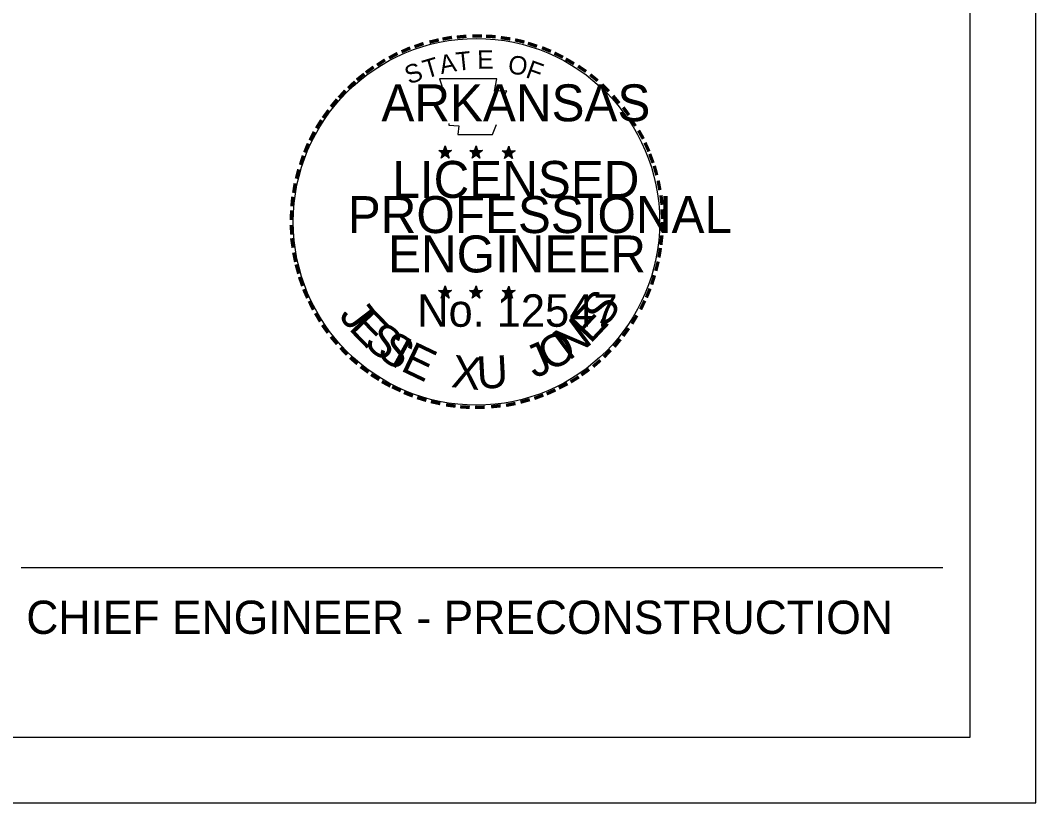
# Model space of a CAD drawing. Extents: x -819161 to 80911, y -6604 to 768454.
# Drawn here: x 48407 to 52278, y -340 to 2641 of the extents above; entities that cross this region are included whole.
import ezdxf

# ---------------------------------------------------------------- set-up
doc = ezdxf.new("R2010")
doc.units = 0
for name, color, linetype in [('29', 7, 'Continuous'), ('31', 7, 'Continuous'), ('Default', 7, 'Continuous'), ('DSN_DRFT_Junk-No-Plot', 7, 'Continuous'), ('SHET_Border-Lines', 7, 'Continuous')]:
    doc.layers.add(name, color=color, linetype=linetype)

msp = doc.modelspace()

# ---------------------------------------------------------------- linework, layer by layer
at = {"layer": '29'}
for p, q in [((50002.4, 2144.7), (50027, 2136.8)), ((50002.4, 2144.7), (50020.5, 2141.8)), ((50002.4, 2144.7), (50019.1, 2136)), ((50011.8, 2115.8), (50027, 2136.8)), ((50011.8, 2115.8), (50020.5, 2133.1)), ((50011.8, 2115.8), (50026.3, 2131)), ((50027, 2162.8), (50024.1, 2144.7)), ((50042.2, 2115.8), (50026.3, 2131)), ((50027, 2136.8), (50027, 2162.8)), ((50027, 2162.8), (50030.6, 2145.5)), ((50050.9, 2144.7), (50027, 2136.8)), ((50042.2, 2115.8), (50027, 2136.8)), ((50050.9, 2144.7), (50031.4, 2141.1)), ((50042.2, 2115.8), (50032.1, 2136)), ((50050.9, 2144.7), (50037.2, 2137.5)), ((50120.4, 2144.7), (50145.1, 2136.8)), ((50120.4, 2144.7), (50137.8, 2141.8)), ((50120.4, 2144.7), (50136.4, 2136)), ((50129.1, 2115.8), (50145.1, 2136.8)), ((50129.1, 2115.8), (50138.5, 2133.1)), ((50129.1, 2115.8), (50144.3, 2131)), ((50145.1, 2162.8), (50142.2, 2144.7)), ((50159.5, 2115.8), (50144.3, 2131)), ((50145.1, 2136.8), (50145.1, 2162.8)), ((50145.1, 2162.8), (50148, 2145.5)), ((50169, 2144.7), (50145.1, 2136.8)), ((50159.5, 2115.8), (50145.1, 2136.8)), ((50169, 2144.7), (50148.7, 2141.1)), ((50159.5, 2115.8), (50149.4, 2136)), ((50169, 2144.7), (50154.5, 2137.5)), ((50244.3, 2144), (50268.9, 2136)), ((50244.3, 2144), (50261.7, 2140.4)), ((50244.3, 2144), (50260.9, 2135.3)), ((50253, 2115), (50268.9, 2136)), ((50253, 2115), (50262.4, 2132.4)), ((50253, 2115), (50268.9, 2130.2)), ((50268.9, 2161.4), (50266, 2144)), ((50268.9, 2136), (50268.9, 2161.4)), ((50268.9, 2161.4), (50271.8, 2144)), ((50293.5, 2144), (50268.9, 2136)), ((50283.4, 2115), (50268.9, 2136)), ((50283.4, 2115), (50268.9, 2130.2)), ((50293.5, 2144), (50272.5, 2140.4)), ((50283.4, 2115), (50274, 2135.3)), ((50293.5, 2144), (50278.3, 2136.8)), ((50026.3, 1629.1), (50023.4, 1611.7)), ((50026.3, 1603.8), (50026.3, 1629.1)), ((50026.3, 1629.1), (50029.9, 1611.7)), ((50144.3, 1629.1), (50141.4, 1611.7)), ((50144.3, 1603.8), (50144.3, 1629.1)), ((50144.3, 1629.1), (50147.2, 1611.7)), ((50268.9, 1628.4), (50266, 1611)), ((50268.9, 1603), (50268.9, 1628.4)), ((50268.9, 1628.4), (50271.8, 1611)), ((50001.7, 1611.7), (50026.3, 1603.8)), ((50001.7, 1611.7), (50020.5, 1608.1)), ((50001.7, 1611.7), (50019.1, 1603)), ((50011.8, 1582.8), (50026.3, 1603.8)), ((50011.8, 1582.8), (50020.5, 1600.2)), ((50011.8, 1582.8), (50026.3, 1598.7)), ((50050.9, 1611.7), (50026.3, 1603.8)), ((50042.2, 1582.8), (50026.3, 1603.8)), ((50042.2, 1582.8), (50026.3, 1598)), ((50050.9, 1611.7), (50030.6, 1608.1)), ((50042.2, 1582.8), (50032.1, 1603)), ((50050.9, 1611.7), (50037.2, 1604.5)), ((50119.7, 1611.7), (50144.3, 1603.8)), ((50119.7, 1611.7), (50137.8, 1608.1)), ((50119.7, 1611.7), (50136.4, 1603)), ((50129.1, 1582.8), (50144.3, 1603.8)), ((50129.1, 1582.8), (50137.8, 1600.2)), ((50129.1, 1582.8), (50144.3, 1598.7)), ((50169, 1611.7), (50144.3, 1603.8)), ((50158.8, 1582.8), (50144.3, 1603.8)), ((50158.8, 1582.8), (50144.3, 1598)), ((50169, 1611.7), (50148, 1608.1)), ((50158.8, 1582.8), (50149.4, 1603)), ((50169, 1611.7), (50153.8, 1604.5)), ((50244.3, 1611), (50268.9, 1603)), ((50244.3, 1611), (50261.7, 1607.4)), ((50244.3, 1611), (50260.9, 1602.3)), ((50253, 1582), (50268.9, 1603)), ((50253, 1582), (50262.4, 1599.4)), ((50253, 1582), (50268.9, 1598)), ((50293.5, 1611), (50268.9, 1603)), ((50283.4, 1582), (50268.9, 1603)), ((50283.4, 1582), (50268.9, 1597.3)), ((50293.5, 1611), (50272.5, 1607.4)), ((50283.4, 1582), (50273.2, 1602.3)), ((50293.5, 1611), (50278.3, 1603.8)), ((48410.7, 556.2), (51924.5, 556.2))]:
    msp.add_line(p, q, dxfattribs=at)
for points in [[(50005.3, 2417.7), (50024.1, 2359.1)], [(50252.2, 2353.3), (50262.4, 2372.8), (50214.6, 2371.4), (50224, 2417.7), (50005.3, 2417.7)], [(50040.1, 2247.6), (50040.1, 2241), (50079.2, 2239.6), (50075.5, 2206.3), (50207.3, 2206.3), (50221.8, 2243.9)], [(50026.3, 1629.1), (50042.2, 1582.8), (50001.7, 1611.7), (50050.9, 1611.7), (50011.8, 1582.8), (50026.3, 1629.1)], [(50268.9, 1628.4), (50283.4, 1582), (50244.3, 1611), (50293.5, 1611), (50253, 1582), (50268.9, 1628.4)]]:
    msp.add_lwpolyline(points, dxfattribs=at)
for centre, radius in [((50146, 1873.2), 698.5), ((50026.4, 2136.7), 12.1), ((50026.4, 2136.7), 10.2), ((50026.4, 2136.7), 8.15), ((50026.4, 2136.7), 6.97), ((50026.4, 2136.7), 5.26), ((50026.4, 2136.7), 3.49), ((50026.4, 2136.7), 2.09), ((50143.9, 2136.7), 12.1), ((50143.9, 2136.7), 10.2), ((50143.9, 2136.7), 8.15), ((50143.9, 2136.7), 6.97), ((50143.9, 2136.7), 5.26), ((50143.9, 2136.7), 3.49), ((50143.9, 2136.7), 2.09), ((50268.1, 2135.8), 12.1), ((50268.1, 2135.8), 10.2), ((50268.1, 2135.8), 8.15), ((50268.1, 2135.8), 6.97), ((50268.1, 2135.8), 5.26), ((50268.1, 2135.8), 3.49), ((50268.1, 2135.8), 2.09), ((50026.1, 1603.6), 12.1), ((50026.1, 1603.6), 10.2), ((50026.1, 1603.6), 8.15), ((50026.1, 1603.6), 6.97), ((50026.1, 1603.6), 5.26), ((50026.1, 1603.6), 3.49), ((50026.1, 1603.6), 2.09), ((50143.6, 1603.6), 12.1), ((50143.6, 1603.6), 10.2), ((50143.6, 1603.6), 8.15), ((50143.6, 1603.6), 6.97), ((50143.6, 1603.6), 5.26), ((50143.6, 1603.6), 3.49), ((50143.6, 1603.6), 2.09), ((50268, 1602.9), 12.1), ((50268, 1602.9), 10.2), ((50268, 1602.9), 8.15), ((50268, 1602.9), 6.97), ((50268, 1602.9), 5.26), ((50268, 1602.9), 3.49), ((50268, 1602.9), 2.09)]:
    msp.add_circle(centre, radius, dxfattribs=at)
at = {"layer": '31'}
for points in [[(50027, 2162.8), (50042.2, 2115.8), (50002.4, 2144.7), (50050.9, 2144.7), (50011.8, 2115.8), (50027, 2162.8)], [(50145.1, 2162.8), (50159.5, 2115.8), (50120.4, 2144.7), (50169, 2144.7), (50129.1, 2115.8), (50145.1, 2162.8)], [(50268.9, 2161.4), (50283.4, 2115), (50244.3, 2144), (50293.5, 2144), (50253, 2115), (50268.9, 2161.4)], [(50144.3, 1629.1), (50158.8, 1582.8), (50119.7, 1611.7), (50169, 1611.7), (50129.1, 1582.8), (50144.3, 1629.1)]]:
    msp.add_lwpolyline(points, dxfattribs=at)
at = {"layer": 'Default'}
msp.add_lwpolyline([(35278.1, 10659.9), (35278.1, -340.1), (52278.1, -340.1), (52278.1, 10659.9)], close=True, dxfattribs=at)
at = {"layer": 'DSN_DRFT_Junk-No-Plot'}
msp.add_lwpolyline([(35278.1, -340.1), (52278.1, -340.1), (52278.1, 10659.9), (35278.1, 10659.9)], close=True, dxfattribs=at)
at = {"layer": 'SHET_Border-Lines'}
msp.add_lwpolyline([(35528.1, -90.1), (52028.1, -90.1), (52028.1, 10409.9), (35528.1, 10409.9)], close=True, dxfattribs=at)
msp.add_lwpolyline([(35528.1, -90.1), (52028.1, -90.1), (52028.1, 10409.9), (35528.1, 10409.9)], close=True, dxfattribs=at)

# ---------------------------------------------------------------- texts
at = {"layer": '29'}
for s, height, rotation, p in [('-', 112.6, 19.1761, (49917.7, 2497.4)), ('-', 112.6, 13.6301, (49970.5, 2514.1)), ('-', 112.6, 10.2193, (50017.6, 2525.6)), ('-', 112.6, 5.8968, (50069, 2532.9)), ('-', 112.6, 0.1862, (50123.3, 2538)), ('-', 112.6, 357.743, (50174, 2537.2)), ('-', 112.6, 352.1617, (50226.2, 2532.9)), ('-', 112.6, 347.2049, (50276.9, 2525.6)), ('-', 112.6, 342.3362, (50322.5, 2514.1)), ('-', 112.6, 28.7918, (49827.9, 2456.1)), ('-', 112.6, 24.3072, (49872.1, 2478.6)), ('T', 70.4, 6.0228, (50071.2, 2448.2)), ('E', 70.4, 0.8323, (50149.4, 2456.1)), ('-', 112.6, 337.8551, (50373.2, 2498.9)), ('-', 112.6, 334.1211, (50418.1, 2480)), ('-', 112.6, 34.0636, (49785.9, 2430.1)), ('S', 70.4, 21.594, (49889.4, 2395.3)), ('T', 70.4, 16.4036, (49953.9, 2418.5)), ('A', 70.4, 11.2132, (50011.8, 2435.8)), ('O', 70.4, 350.4515, (50262.4, 2440.9)), ('F', 70.4, 340.0707, (50329.7, 2425)), ('-', 112.6, 329.6409, (50458.6, 2459.7)), ('-', 112.6, 38.9507, (49712, 2375.7)), ('-', 112.6, 36.2317, (49744.6, 2402.5)), ('-', 112.6, 325.8627, (50503.5, 2434.4)), ('-', 112.6, 320.5297, (50547, 2404.7)), ('-', 112.6, 42.9622, (49681.6, 2346)), ('-', 112.6, 315.5786, (50589, 2369.9)), ('-', 112.6, 48.4231, (49649.7, 2312)), ('-', 112.6, 50.6142, (49620.8, 2278.7)), ('-', 112.6, 309.8797, (50628.8, 2330.8)), ('-', 112.6, 54.2325, (49592.5, 2238.1)), ('-', 112.6, 306.6522, (50666.5, 2288.8)), ('-', 112.6, 58.0706, (49569.3, 2201.2)), ('-', 98.5, 303.6753, (50699.8, 2249)), ('-', 112.6, 62.8713, (49546.9, 2157.8)), ('-', 112.6, 299.6684, (50723, 2205.6)), ('-', 112.6, 67.7743, (49528.8, 2115)), ('-', 112.6, 294.6628, (50746.1, 2162.8)), ('-', 112.6, 290.5728, (50763.5, 2123)), ('-', 112.6, 72.3945, (49514.3, 2070.9)), ('-', 112.6, 75.461, (49499.8, 2020.2)), ('-', 112.6, 285.1233, (50780.2, 2081.7)), ('-', 112.6, 81.2013, (49491.1, 1970.2)), ('-', 112.6, 280.5493, (50794.7, 2028.9)), ('-', 112.6, 276.5962, (50805.5, 1976)), ('-', 112.6, 85.1863, (49485.3, 1921.7)), ('-', 112.6, 89.0622, (49483.9, 1872.4)), ('-', 112.6, 274.3301, (50809.9, 1924.6)), ('-', 112.6, 94.1959, (49486.1, 1821)), ('-', 112.6, 269.9407, (50812, 1879.7)), ('-', 112.6, 263.5172, (50810.6, 1833.3)), ('-', 112.6, 98.9479, (49491.1, 1774.7)), ('-', 112.6, 101.7149, (49500.6, 1722.5)), ('-', 112.6, 260.9953, (50805.5, 1787)), ('-', 112.6, 105.4578, (49512.1, 1680.5)), ('-', 112.6, 255.7626, (50798.3, 1739.2)), ('-', 112.6, 109.0874, (49526.6, 1636.4)), ('-', 112.6, 252.8681, (50785.2, 1688.5)), ('-', 112.6, 114.0643, (49544.7, 1594.4)), ('S', 123.7, 53.9986, (50636.3, 1465.2)), ('-', 112.6, 247.8887, (50770, 1641.4)), ('-', 112.6, 115.7289, (49566.5, 1550.9)), ('J', 123.7, 307.2662, (49618.8, 1515.4)), ('E', 123.7, 46.8094, (50580.1, 1405.7)), ('-', 112.6, 244.6197, (50751.2, 1597.3)), ('-', 112.6, 120.4471, (49591.8, 1509.6)), ('E', 123.7, 314.2033, (49655.6, 1464.9)), ('-', 112.6, 239.0712, (50723.7, 1544.4)), ('-', 112.6, 125.8934, (49619.3, 1470.5)), ('S', 123.7, 321.0594, (49712.2, 1405.7)), ('N', 123.7, 36.7249, (50498.5, 1342.2)), ('-', 112.6, 233.8452, (50695.4, 1498.8)), ('-', 112.6, 130.7181, (49652.6, 1430.7)), ('S', 123.7, 324.4537, (49760.7, 1366.5)), ('O', 123.7, 28.7821, (50424, 1299.8)), ('-', 112.6, 134.2238, (49688.8, 1393)), ('I', 123.7, 331.1686, (49811.8, 1330.9)), ('E', 123.7, 334.487, (49852.7, 1308.2)), ('J', 123.7, 23.3052, (50366.6, 1275.3)), ('-', 112.6, 231.2538, (50665, 1458.2)), ('-', 112.6, 138.9338, (49725.8, 1360.4)), ('X', 123.7, 353.7858, (50047, 1243.9)), ('U', 123.7, 3.0061, (50149.9, 1236.2)), ('-', 112.6, 225.7653, (50631, 1419.1)), ('-', 112.6, 144.6463, (49764.9, 1331.5)), ('-', 112.6, 215.7363, (50555.7, 1350.3)), ('-', 112.6, 221.0851, (50594.8, 1382.9)), ('-', 112.6, 148.0898, (49804, 1305.4)), ('-', 112.6, 212.2491, (50518.7, 1322.8)), ('-', 112.6, 151.5704, (49844.5, 1282.2)), ('-', 112.6, 154.6002, (49882.2, 1265.6)), ('-', 112.6, 207.3568, (50478.9, 1298.2)), ('-', 112.6, 158.5612, (49925.6, 1247.5)), ('-', 112.6, 162.7983, (49974.2, 1232.3)), ('-', 112.6, 195.4743, (50344.2, 1239.5)), ('-', 112.6, 200.7184, (50392, 1256.2)), ('-', 112.6, 204.2516, (50435.5, 1275)), ('-', 112.6, 167.5555, (50024.1, 1221.4)), ('-', 112.6, 173.1155, (50078.4, 1213.4)), ('-', 112.6, 176.5183, (50129.9, 1209.2)), ('-', 112.6, 181.5918, (50182.8, 1210.7)), ('-', 112.6, 185.8167, (50240.7, 1216.3)), ('-', 112.6, 191.2858, (50292.8, 1225))]:
    msp.add_text(s, height=height, rotation=rotation, dxfattribs=at).set_placement(p)
for s, height, p in [('ARKANSAS', 140.78, (49783.7, 2256.3)), ('LICENSED', 140.78, (49825.7, 1964.4)), ('PROFESSIONAL', 140.779, (49655.5, 1830.4)), ('ENGINEER', 140.78, (49809, 1680.5)), ('No. 12547', 123.67, (49920.3, 1473.4)), ('CHIEF ENGINEER - PRECONSTRUCTION', 126.702, (48429.7, 303))]:
    msp.add_text(s, height=height, dxfattribs=at).set_placement(p)

doc.saveas('drawing.dxf')
